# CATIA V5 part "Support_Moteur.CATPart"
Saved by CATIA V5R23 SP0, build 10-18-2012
Part number: Support_Moteur
Material "Aluminium": density 2710 kg/m3, Young's modulus 7e+10 Pa, Poisson ratio 0.346, thermal expansion 2.36e-05 1/K
Bounding box of the stored display mesh (mm): x -45 to 45, y 0 to 75, z -7.5 to 7.5
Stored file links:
  P:\eleve\Support_Moteur.CATPart
  C:\Program Files\Dassault Systemes\B23\win_b64\startup\materials\French\Catalog.CATMaterial
  d:\catia_soft\intel_a\reffiles\standard\MetricThickPitch.txt
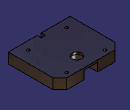
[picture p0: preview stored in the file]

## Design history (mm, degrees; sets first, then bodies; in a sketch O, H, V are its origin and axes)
Body1 (main body)
  Sketch1 on xy-plane, origin (0, 0, 0), H (1, 0, 0), V (0, 1, 0)
    point P1 (-45, 0)
    line L1 (-45, 0) -> (45, 0)
    line L2 (45, 0) -> (45, 75)
    line L3 (45, 75) -> (-45, 75)
    line L4 (-45, 75) -> (-45, 0)
    reference intersected line E1 through (0, 0) direction (0, 1) from yz-plane
    reference intersected line E2 through (0, 0) direction (-1, 0) from zx-plane
    distance L4 L2 = 90
    distance E2 L3 = 75
    coincidence: P1 H
    horizontal: L1 H, L3 H
    vertical: L2 V, L4 V
    symmetry: L4 L2 E1
  Pad1: profile Sketch1, direction (0, 0, 1), length 7.5, mirrored extent
  Sketch2 "Esquisse.2" on face of Pad1, origin (-2.0176, 52.3359, -7.5), H (1, 0, 0), V (0, -1, 0)
    point P1 (2.0176, -2.6641)
    reference intersected line E1 through (2.0176, 0) direction (0, 1) from yz-plane
    reference intersected line E2 (-42.9824, 52.3359) -> (47.0176, 52.3359) from face of Pad1
    distance E2 P1 = 55
    coincidence: P1 E1
  Hole1 "Trou.1": placed by Sketch2, at (0, 55, -7.5) direction (0, 0, 1), diameter 14, through (limit type 3)
  Sketch3 "Esquisse.3" on xy-plane, origin (0, 0, 0), H (1, 0, 0), V (0, 1, 0)
    line L1 (-3, -4) -> (3, -4)
    line L2 (3, -4) -> (3, 6)
    line L3 (3, 6) -> (-3, 6)
    line L4 (-3, 6) -> (-3, -4)
    reference intersected line E1 through (0, 0) direction (0, 1) from yz-plane
    reference intersected line E2 (45, 0) -> (-45, 0) from face of Pad1
    distance L4 L2 = 6
    distance L3 E2 = 6
    distance L1 H = 4
    horizontal: L1 H, L3 H
    vertical: L2 V, L4 V
    symmetry: L4 L2 E1
  Pocket1: profile Sketch3, direction (0, 0, -1), through (limit type 3), opposite side through (limit type 3)
  Sketch4 "Esquisse.4" on face of Pad1, origin (-33.8023, 0, -1.5862), H (1, 0, 0), V (0, 0, 1)
    point P1 (-1.1977, 1.5862)
    reference intersected line E1 through (0, 1.5862) direction (-1, 0) from xy-plane
    reference intersected line E2 through (33.8023, 0) direction (0, 1) from yz-plane
    distance P1 E2 = 35
    coincidence: P1 E1
  Hole2 "Trou.2": placed by Sketch4, at (-35, 0, 0) direction (0, 1, 0), diameter 4.134, depth 12, V-bottom angle 120, threaded "M5", thread diameter 5, thread depth 10, pitch 0.8
  Mirror1 "Symétrie.1": of Hole2, about yz-plane
  Sketch5 "Esquisse.5" on face of Pad1, origin (-35.1004, 62.4395, -7.5), H (1, 0, 0), V (0, -1, 0)
    point P1 (7.1004, -5.5605)
    reference intersected line E1 through (35.1004, 0) direction (0, 1) from yz-plane
    reference projected point E2 (35.1004, 7.4395) from axis of face of Hole1
    distance P1 E1 = 28
    distance P1 E2 V = 13
  Hole3 "Trou.3": placed by Sketch5, at (-28, 68, -7.5) direction (0, 0, 1), diameter 4.134, through (limit type 3), counterbore diameter 7, counterbore depth 10
  RectPattern1: of Hole3, direction 1 instances 2, spacing 56, along edge [face of Pad1 | face of Pad1] reversed, direction 2 instances 2, spacing 56, along edge [face of Pad1 | face of Pad1]
  Chamfer1: length 10, angle 45, on edge [face of Pad1 | face of Pad1] (x2)
  Sketch6 "Esquisse.6" on face of Pad1, origin (0, 0, -7.5), H (1, 0, 0), V (0, -1, 0)
    construction line L1 (0, -55) -> (0, -77)
    point P1 (0, -55)
    point P2 (0, -77)
    line L2 (10, -55) -> (10, -77)
    line L3 (-10, -77) -> (-10, -55)
    arc A1 centre (0, -77) radius 10 from (10, -77) to (-10, -77) cw
    arc A2 centre (0, -55) radius 10 from (-10, -55) to (10, -55) cw
    reference projected point E1 (0, -55) from axis of face of Hole1
    reference intersected line E2 (45, -75) -> (-45, -75) from face of Pad1
    radius A2 = 10
    distance P2 E2 = 2
    vertical: L1 V
    tangency: A1 L2, A2 L2, A1 L3, A2 L3
    parallelism: L1 L2
    coincidence: P1 E1
  Pocket2: profile Sketch6, direction (0, 0, 1), length 12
